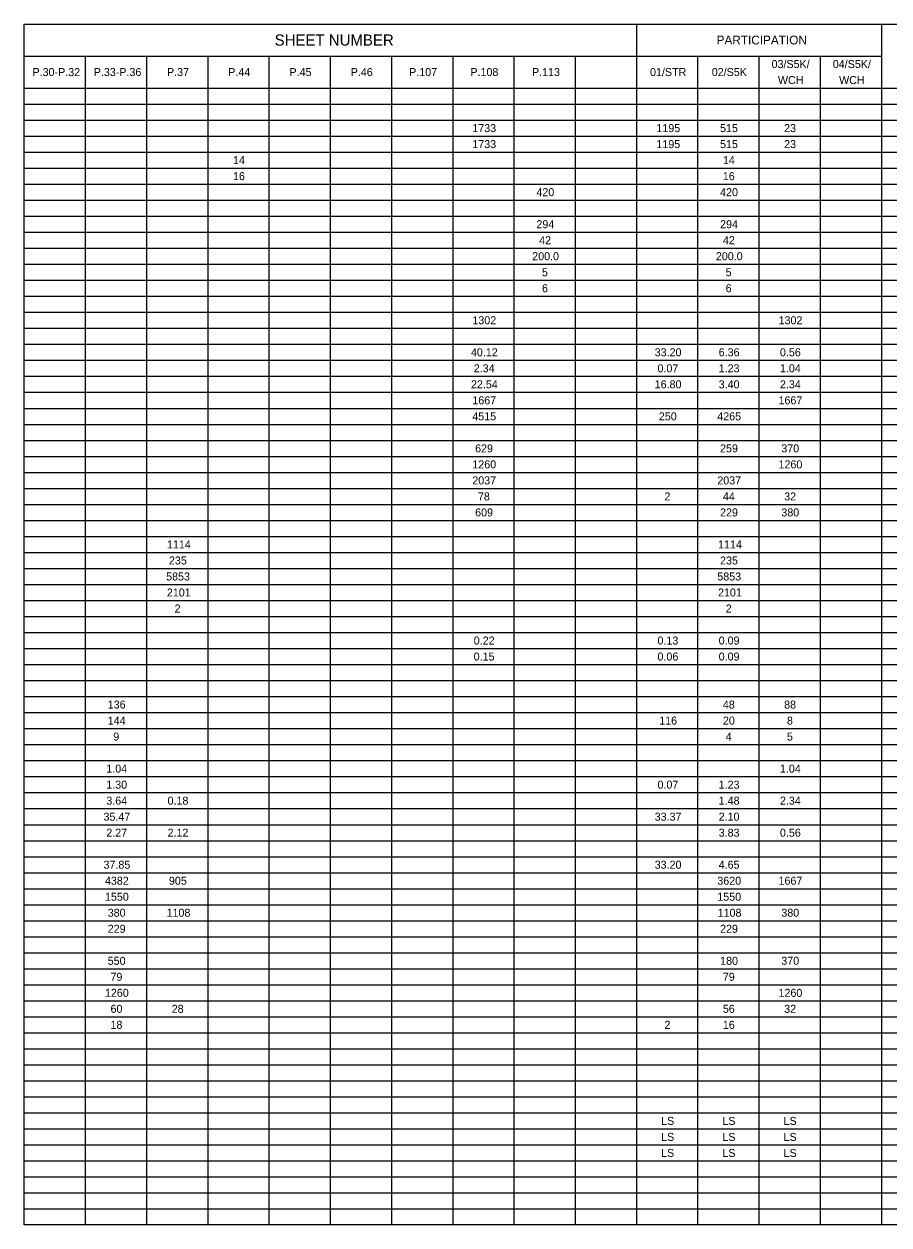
# Model space of a CAD drawing. Extents: x 12522 to 13018, y 1124 to 1902.
# Drawn here: x 12721.3 to 12736.42, y 1804.65 to 1825.65 of the extents above; entities that cross this region are included whole.
import ezdxf

# ---------------------------------------------------------------- set-up
doc = ezdxf.new("R2010")
doc.units = 0
for name, color, linetype in [('SC_Scratch1', 7, 'Continuous'), ('SH_Data', 7, 'Continuous'), ('SH_Text', 7, 'Continuous')]:
    doc.layers.add(name, color=color, linetype=linetype)

msp = doc.modelspace()

# ---------------------------------------------------------------- linework, layer by layer
at = {"layer": 'SC_Scratch1'}
msp.add_lwpolyline([(12721.301, 1825.65), (12751.801, 1825.65), (12751.801, 1804.65), (12721.301, 1804.65)], close=True, dxfattribs=at)
at = {"layer": 'SH_Data'}
for p, q in [((12732.006, 1825.65), (12732.006, 1804.65)), ((12736.289, 1825.65), (12736.289, 1804.65)), ((12721.301, 1825.09), (12736.289, 1825.09)), ((12722.371, 1825.09), (12722.371, 1804.65)), ((12723.442, 1825.09), (12723.442, 1804.65)), ((12724.512, 1825.09), (12724.512, 1804.65)), ((12725.583, 1825.09), (12725.583, 1804.65)), ((12726.654, 1825.09), (12726.654, 1804.65)), ((12727.724, 1825.09), (12727.724, 1804.65)), ((12728.795, 1825.09), (12728.795, 1804.65)), ((12729.865, 1825.09), (12729.865, 1804.65)), ((12730.936, 1825.09), (12730.936, 1804.65)), ((12733.077, 1825.09), (12733.077, 1804.65)), ((12734.148, 1825.09), (12734.148, 1804.65)), ((12735.218, 1825.09), (12735.218, 1804.65)), ((12721.301, 1824.53), (12751.804, 1824.53)), ((12721.301, 1824.25), (12751.804, 1824.25)), ((12721.301, 1823.97), (12751.804, 1823.97)), ((12721.301, 1823.69), (12751.804, 1823.69)), ((12721.301, 1823.41), (12751.804, 1823.41)), ((12721.301, 1823.13), (12751.804, 1823.13)), ((12721.301, 1822.85), (12751.804, 1822.85)), ((12721.301, 1822.57), (12751.804, 1822.57)), ((12721.301, 1822.29), (12751.804, 1822.29)), ((12721.301, 1822.01), (12751.804, 1822.01)), ((12721.301, 1821.73), (12751.804, 1821.73)), ((12721.301, 1821.45), (12751.804, 1821.45)), ((12721.301, 1821.17), (12751.804, 1821.17)), ((12721.301, 1820.89), (12751.804, 1820.89)), ((12721.301, 1820.61), (12751.804, 1820.61)), ((12721.301, 1820.33), (12751.804, 1820.33)), ((12721.301, 1820.05), (12751.804, 1820.05)), ((12721.301, 1819.77), (12751.804, 1819.77)), ((12721.301, 1819.49), (12751.804, 1819.49)), ((12721.301, 1819.21), (12751.804, 1819.21)), ((12721.301, 1818.93), (12751.804, 1818.93)), ((12721.301, 1818.65), (12751.804, 1818.65)), ((12721.301, 1818.37), (12751.804, 1818.37)), ((12721.301, 1818.09), (12751.804, 1818.09)), ((12721.301, 1817.81), (12751.804, 1817.81)), ((12721.301, 1817.53), (12751.804, 1817.53)), ((12721.301, 1817.25), (12751.804, 1817.25)), ((12721.301, 1816.97), (12751.804, 1816.97)), ((12721.301, 1816.69), (12751.804, 1816.69)), ((12721.301, 1816.41), (12751.804, 1816.41)), ((12721.301, 1816.13), (12751.804, 1816.13)), ((12721.301, 1815.85), (12751.804, 1815.85)), ((12721.301, 1815.57), (12751.804, 1815.57)), ((12721.301, 1815.29), (12751.804, 1815.29)), ((12721.301, 1815.01), (12751.804, 1815.01)), ((12721.301, 1814.73), (12751.804, 1814.73)), ((12721.301, 1814.45), (12751.804, 1814.45)), ((12721.301, 1814.17), (12751.804, 1814.17)), ((12721.301, 1813.89), (12751.804, 1813.89)), ((12721.301, 1813.61), (12751.804, 1813.61)), ((12721.301, 1813.33), (12751.804, 1813.33)), ((12721.301, 1813.05), (12751.804, 1813.05)), ((12721.301, 1812.77), (12751.804, 1812.77)), ((12721.301, 1812.49), (12751.804, 1812.49)), ((12721.301, 1812.21), (12751.804, 1812.21)), ((12721.301, 1811.93), (12751.804, 1811.93)), ((12721.301, 1811.65), (12751.804, 1811.65)), ((12721.301, 1811.37), (12751.804, 1811.37)), ((12721.301, 1811.09), (12751.804, 1811.09)), ((12721.301, 1810.81), (12751.804, 1810.81)), ((12721.301, 1810.53), (12751.804, 1810.53)), ((12721.301, 1810.25), (12751.804, 1810.25)), ((12721.301, 1809.97), (12751.804, 1809.97)), ((12721.301, 1809.69), (12751.804, 1809.69)), ((12721.301, 1809.41), (12751.804, 1809.41)), ((12721.301, 1809.13), (12751.804, 1809.13)), ((12721.301, 1808.85), (12751.804, 1808.85)), ((12721.301, 1808.57), (12751.804, 1808.57)), ((12721.301, 1808.29), (12751.804, 1808.29)), ((12721.301, 1808.01), (12751.804, 1808.01)), ((12721.301, 1807.73), (12751.804, 1807.73)), ((12721.301, 1807.45), (12751.804, 1807.45)), ((12721.301, 1807.17), (12751.804, 1807.17)), ((12721.301, 1806.89), (12751.804, 1806.89)), ((12721.301, 1806.61), (12751.804, 1806.61)), ((12721.301, 1806.33), (12751.804, 1806.33)), ((12721.301, 1806.05), (12751.804, 1806.05)), ((12721.301, 1805.77), (12751.804, 1805.77)), ((12721.301, 1805.49), (12751.804, 1805.49)), ((12721.301, 1805.21), (12751.804, 1805.21)), ((12721.301, 1804.93), (12751.804, 1804.93))]:
    msp.add_line(p, q, dxfattribs=at)

# ---------------------------------------------------------------- texts
at = {"layer": 'SH_Text'}
for s, height, p in [('SHEET NUMBER', 0.196, (12725.682, 1825.272)), ('PARTICIPATION', 0.154, (12733.408, 1825.293)), ('03/S5K/', 0.14, (12734.37, 1824.88)), ('04/S5K/', 0.14, (12735.44, 1824.88)), ('P.30-P.32', 0.14, (12721.449, 1824.74)), ('P.33-P.36', 0.14, (12722.519, 1824.74)), ('P.37', 0.14, (12723.8, 1824.74)), ('P.44', 0.14, (12724.871, 1824.74)), ('P.45', 0.14, (12725.941, 1824.74)), ('P.46', 0.14, (12727.012, 1824.74)), ('P.107', 0.14, (12728.033, 1824.74)), ('P.108', 0.14, (12729.104, 1824.74)), ('P.113', 0.14, (12730.181, 1824.74)), ('01/STR', 0.14, (12732.245, 1824.74)), ('02/S5K', 0.14, (12733.324, 1824.74)), ('WCH', 0.14, (12734.48, 1824.6)), ('WCH', 0.14, (12735.55, 1824.6)), ('1733', 0.14, (12729.138, 1823.76)), ('1195', 0.14, (12732.356, 1823.76)), ('515', 0.14, (12733.469, 1823.76)), ('23', 0.14, (12734.589, 1823.76)), ('1733', 0.14, (12729.138, 1823.48)), ('1195', 0.14, (12732.356, 1823.48)), ('515', 0.14, (12733.469, 1823.48)), ('23', 0.14, (12734.589, 1823.48)), ('14', 0.14, (12724.954, 1823.2)), ('14', 0.14, (12733.519, 1823.2)), ('16', 0.14, (12724.954, 1822.92)), ('16', 0.14, (12733.518, 1822.92)), ('420', 0.14, (12730.258, 1822.64)), ('420', 0.14, (12733.47, 1822.64)), ('294', 0.14, (12730.258, 1822.08)), ('294', 0.14, (12733.47, 1822.08)), ('42', 0.14, (12730.307, 1821.8)), ('42', 0.14, (12733.519, 1821.8)), ('200.0', 0.14, (12730.185, 1821.52)), ('200.0', 0.14, (12733.396, 1821.52)), ('5', 0.14, (12730.355, 1821.24)), ('5', 0.14, (12733.567, 1821.24)), ('6', 0.14, (12730.356, 1820.96)), ('6', 0.14, (12733.567, 1820.96)), ('1302', 0.14, (12729.139, 1820.4)), ('1302', 0.14, (12734.492, 1820.4)), ('40.12', 0.14, (12729.114, 1819.84)), ('33.20', 0.14, (12732.326, 1819.84)), ('6.36', 0.14, (12733.445, 1819.84)), ('0.56', 0.14, (12734.516, 1819.84)), ('2.34', 0.14, (12729.163, 1819.56)), ('0.07', 0.14, (12732.375, 1819.56)), ('1.23', 0.14, (12733.445, 1819.56)), ('1.04', 0.14, (12734.516, 1819.56)), ('22.54', 0.14, (12729.114, 1819.28)), ('16.80', 0.14, (12732.326, 1819.28)), ('3.40', 0.14, (12733.445, 1819.28)), ('2.34', 0.14, (12734.516, 1819.28)), ('1667', 0.14, (12729.138, 1819)), ('1667', 0.14, (12734.491, 1819)), ('4515', 0.14, (12729.138, 1818.72)), ('250', 0.14, (12732.399, 1818.72)), ('4265', 0.14, (12733.42, 1818.72)), ('629', 0.14, (12729.187, 1818.16)), ('259', 0.14, (12733.469, 1818.16)), ('370', 0.14, (12734.54, 1818.16)), ('1260', 0.14, (12729.138, 1817.88)), ('1260', 0.14, (12734.491, 1817.88)), ('2037', 0.14, (12729.138, 1817.6)), ('2037', 0.14, (12733.421, 1817.6)), ('78', 0.14, (12729.236, 1817.32)), ('2', 0.14, (12732.497, 1817.32)), ('44', 0.14, (12733.519, 1817.32)), ('32', 0.14, (12734.59, 1817.32)), ('609', 0.14, (12729.187, 1817.04)), ('229', 0.14, (12733.469, 1817.04)), ('380', 0.14, (12734.54, 1817.04)), ('1114', 0.14, (12723.799, 1816.48)), ('1114', 0.14, (12733.434, 1816.48)), ('235', 0.14, (12723.834, 1816.2)), ('235', 0.14, (12733.469, 1816.2)), ('5853', 0.14, (12723.785, 1815.92)), ('5853', 0.14, (12733.421, 1815.92)), ('2101', 0.14, (12723.798, 1815.64)), ('2101', 0.14, (12733.433, 1815.64)), ('2', 0.14, (12723.933, 1815.36)), ('2', 0.14, (12733.568, 1815.36)), ('0.22', 0.14, (12729.163, 1814.8)), ('0.13', 0.14, (12732.375, 1814.8)), ('0.09', 0.14, (12733.445, 1814.8)), ('0.15', 0.14, (12729.162, 1814.52)), ('0.06', 0.14, (12732.375, 1814.52)), ('0.09', 0.14, (12733.445, 1814.52)), ('136', 0.14, (12722.764, 1813.68)), ('48', 0.14, (12733.518, 1813.68)), ('88', 0.14, (12734.589, 1813.68)), ('144', 0.14, (12722.764, 1813.4)), ('116', 0.14, (12732.405, 1813.4)), ('20', 0.14, (12733.519, 1813.4)), ('8', 0.14, (12734.638, 1813.4)), ('9', 0.14, (12722.861, 1813.12)), ('4', 0.14, (12733.568, 1813.12)), ('5', 0.14, (12734.638, 1813.12)), ('1.04', 0.14, (12722.739, 1812.56)), ('1.04', 0.14, (12734.516, 1812.56)), ('1.30', 0.14, (12722.739, 1812.28)), ('0.07', 0.14, (12732.375, 1812.28)), ('1.23', 0.14, (12733.445, 1812.28)), ('3.64', 0.14, (12722.739, 1812)), ('0.18', 0.14, (12723.81, 1812)), ('1.48', 0.14, (12733.445, 1812)), ('2.34', 0.14, (12734.516, 1812)), ('35.47', 0.14, (12722.69, 1811.72)), ('33.37', 0.14, (12732.326, 1811.72)), ('2.10', 0.14, (12733.445, 1811.72)), ('2.27', 0.14, (12722.739, 1811.44)), ('2.12', 0.14, (12723.81, 1811.44)), ('3.83', 0.14, (12733.445, 1811.44)), ('0.56', 0.14, (12734.516, 1811.44)), ('37.85', 0.14, (12722.69, 1810.88)), ('33.20', 0.14, (12732.326, 1810.88)), ('4.65', 0.14, (12733.445, 1810.88)), ('4382', 0.14, (12722.715, 1810.6)), ('905', 0.14, (12723.834, 1810.6)), ('3620', 0.14, (12733.421, 1810.6)), ('1667', 0.14, (12734.491, 1810.6)), ('1550', 0.14, (12722.715, 1810.32)), ('1550', 0.14, (12733.421, 1810.32)), ('380', 0.14, (12722.764, 1810.04)), ('1108', 0.14, (12723.792, 1810.04)), ('1108', 0.14, (12733.427, 1810.04)), ('380', 0.14, (12734.54, 1810.04)), ('229', 0.14, (12722.764, 1809.76)), ('229', 0.14, (12733.469, 1809.76)), ('550', 0.14, (12722.764, 1809.2)), ('180', 0.14, (12733.47, 1809.2)), ('370', 0.14, (12734.54, 1809.2)), ('79', 0.14, (12722.812, 1808.92)), ('79', 0.14, (12733.518, 1808.92)), ('1260', 0.14, (12722.715, 1808.64)), ('1260', 0.14, (12734.491, 1808.64)), ('60', 0.14, (12722.813, 1808.36)), ('28', 0.14, (12723.883, 1808.36)), ('56', 0.14, (12733.518, 1808.36)), ('32', 0.14, (12734.59, 1808.36)), ('18', 0.14, (12722.812, 1808.08)), ('2', 0.14, (12732.497, 1808.08)), ('16', 0.14, (12733.518, 1808.08)), ('LS', 0.14, (12732.439, 1806.4)), ('LS', 0.14, (12733.509, 1806.4)), ('LS', 0.14, (12734.58, 1806.4)), ('LS', 0.14, (12732.439, 1806.12)), ('LS', 0.14, (12733.509, 1806.12)), ('LS', 0.14, (12734.58, 1806.12)), ('LS', 0.14, (12732.439, 1805.84)), ('LS', 0.14, (12733.509, 1805.84)), ('LS', 0.14, (12734.58, 1805.84))]:
    msp.add_text(s, height=height, dxfattribs=at).set_placement(p)

doc.saveas('drawing.dxf')
